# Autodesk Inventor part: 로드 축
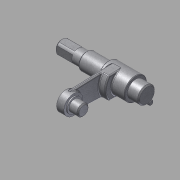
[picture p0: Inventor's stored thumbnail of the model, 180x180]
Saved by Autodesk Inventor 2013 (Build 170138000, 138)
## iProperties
Created: 2015-10
Part Number: 로드 축
Document SubType Name: Modeling
Designer: mdu
Density: 1 g/cm^3
Material: 강철, 연강
Mass: 20.0934 g
Surface Area: 69.4485 cm^2
Volume: 20.0934 cm^3
Author: mdu
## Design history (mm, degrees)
sketch "스케치1"
  geometry: L1 (-3.325, 13.5)-(-3.325, -13.5) reference; L2 (48.675, -15.7)-(48.675, 15.7) reference; L3 (48.675, 0)-(-26.325, 0); L4 (39.675, -18.06)-(39.675, 18.06) reference; L5 (15.675, 18.855)-(15.675, -18.855) reference; L6 (6.675, 15.7)-(6.675, -15.7) reference; L7 (3.675, -10)-(3.675, 10) reference; L8 (49.675, 7.5)-(39.675, 7.5); L9 (39.675, 7.5)-(39.675, 10); L10 (39.675, 10)-(15.675, 10); L11 (15.675, 10)-(15.675, 7.5); L12 (15.675, 7.5)-(-4.325, 7.5); L13 (-4.325, 7.5)-(-4.325, 6); L14 (-4.325, 6)-(-26.325, 6); L15 (-26.325, 6)-(-26.325, 0); L16 (48.675, 0)-(49.675, 0); L17 (49.675, 0)-(49.675, 7.5); 1 further point
  constraints: 22 end point, 7 perpendicular, 4 point on line, 2 parallel, 1 collinear, 1 midpoint
  dimensions: "d0" = 15 diameter of L8 L3; "d1" = 20 diameter of L10 L3; "d2" = 12 diameter of L14 L3; "d3" = 20 distance of L11.end L12.end; "d4" = 1 distance between parallel lines of L17 L2; "d5" = 75 distance of L3.start L3.end
revolve "회전1" sketch "스케치1" stored, may be unused: angle "d6" = 90 deg
chamfer "모따기1" distance "d7" = 1; stored, may be unused: second distance "d8" = 2, angle "d9" = 45 deg
node "작업 평면1"
sketch "스케치2"
  geometry: 1 further point
sketch "스케치3"
  geometry: L1 (9.993, -0.375)-(8.494, -40.319); L2 (-8.494, -40.319)-(-9.993, -0.375); C1 r 10 at (0, 0) reference; A1 r 8.5 centre (0, -40) between (8.494, -40.319) and (-8.494, -40.319); A2 r 10 centre (0, 0) between (-9.993, -0.375) and (9.993, -0.375) reference; 1 further point
  constraints: 4 end point, 4 point on circle, 4 tangent, 1 centre point, 1 vertical alignment
  dimensions: "d12" = 17 diameter of A1; "d22" = 40 distance of A1.centre A2.centre
  node "투영된 루프1"
extrude "돌출1" join sketch "스케치3" distance "d13" = 6.5; taper "d14" = 0 deg
node "작업 평면3"
  node "작업 평면2"
extrude "돌출2" join sketch "스케치3" stored distance "d17" = 6; taper "d18" = 0 deg
sketch "스케치7"
  geometry: L1 (-9.993, -0.375)-(-8.494, -40.319) reference; L2 (8.494, -40.319)-(9.993, -0.375) reference; A1 r 10 centre (0, 0) between (-9.993, -0.375) and (9.993, -0.375) reference; A2 r 15 centre (0, 0) between (-9.574, -11.547) and (9.574, -11.547); 1 further point
  constraints: 2 point on circle, 2 point on line, 1 centre point, 1 coincident
  dimensions: "d32" = 30 diameter of A2
extrude "돌출6" join sketch "스케치7" distance "d33" = 6; taper "d34" = 0 deg
sketch "스케치5"
  geometry: C1 r 5 at (0, 0) reference; C2 r 6.5 at (0, 0); 1 further point
  constraints: 1 centre point, 1 coincident
  dimensions: "d23" = 13 diameter of C2
  node "참조8"
extrude "돌출4" join sketch "스케치5" distance "d24" = 9; taper "d25" = 0 deg
extrude "돌출5" join sketch "스케치5" distance "d26" = 1; taper "d27" = 0 deg
fillet "모깎기1" dims "d28" = 1
chamfer "모따기2" distance "d29" = 1; stored, may be unused: second distance "d30" = 2, angle "d31" = 45 deg
chamfer "모따기3" distance "d35" = 0.5; stored, may be unused: second distance "d36" = 2, angle "d37" = 45 deg
sketch "스케치8"
  geometry: L1 (-3.25, 5.044)-(3.25, 5.044); L2 (5.044, 3.25)-(5.044, -3.25); L3 (3.25, -5.044)-(-3.25, -5.044); L4 (-5.044, -3.25)-(-5.044, 3.25); 2 further points
  constraints: 8 end point, 6 perpendicular, 1 horizontal, 9 other
  dimensions: "d38" = 6.5 distance of L3.start L3.end
extrude "돌출7" cut sketch "스케치8" distance "d39" = 15; taper "d40" = 0 deg
node "작업 평면4"
sketch "스케치9"
  geometry: L1 (7.66, 6.428)-(25.279, 21.212); L2 (23.973, 23.344)-(1.901, 9.818); L3 (27.152, 19.555)-(9.999, 0.167); L4 (28.659, 0)-(-16.444, 0) reference; C1 r 2 at (25.279, 21.212); A1 r 10 centre (0, 0) between (7.66, 6.428) and (1.901, 9.818) reference; A2 r 2.5 centre (25.279, 21.212) between (23.973, 23.344) and (27.152, 19.555); 1 further point
  constraints: 6 end point, 5 point on circle, 2 centre point, 2 coincident, 2 tangent, 1 point on line
  dimensions: "d42" = 23 distance of L1.start L1.end; "d43" = 5 diameter of A2; "d44" = 17 deg angle of L3 L2; "d45" = 8.5 deg angle of L1 L2 (= 0.5 x d44); "d46" = 40 deg angle of L4 L1; "d54" = 4 diameter of C1
extrude "돌출8" join sketch "스케치9" stored distance "d47" = 3; taper "d48" = 0 deg
extrude "돌출9" join sketch "스케치9" stored distance "d49" = 4; taper "d50" = 0 deg
fillet "모깎기2" dims "d51" = 1
fillet "모깎기3" dims "d52" = 1
fillet "모깎기4" dims "d53" = 1
extrude "돌출10" join sketch "스케치9" stored distance "d55" = 15; taper "d56" = 0 deg
chamfer "모따기4" distance "d57" = 0.5; stored, may be unused: second distance "d58" = 2, angle "d59" = 45 deg
node "솔리드1"
node "참조1"
node "참조2"
node "참조3"
node "참조4"
node "참조5"
node "참조6"
other parameters: "d10" = -8.5, "d15" = -1, "d16" = -3, "d41" = -15
